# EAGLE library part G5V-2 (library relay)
OMRON PCB Relay Source: http://www.omron.com/ecb/products/pdf/en-g5v2.pdf
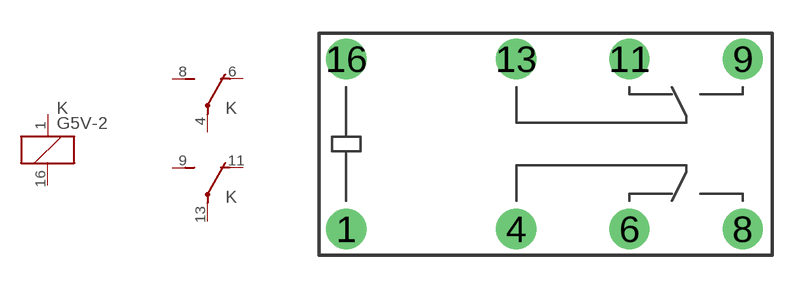
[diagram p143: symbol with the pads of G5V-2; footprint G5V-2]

Designator prefix K; gates A=K 1=U 2=U

## G5V-2 (MPN: G5V-2 5DC; OC_FARNELL: 9949488; OC_NEWARK: 78K5703)  [G5V-2]
1  A:1  pas
4  1:P  pas
6  1:O  pas
8  1:S  pas
9  2:S  pas
11  2:O  pas
13  2:P  pas
16  A:2  pas

## Footprint G5V-2 (pad centres in mm)
OMRON PCB Relay Source: http://www.omron.com/ecb/products/pdf/en-g5v2.pdf
drill 1 pad 1.8 round: 1 -8.89,-3.81; 4 -1.27,-3.81; 6 3.81,-3.81; 8 8.89,-3.81; 9 8.89,3.81; 11 3.81,3.81; 13 -1.27,3.81; 16 -8.89,3.81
